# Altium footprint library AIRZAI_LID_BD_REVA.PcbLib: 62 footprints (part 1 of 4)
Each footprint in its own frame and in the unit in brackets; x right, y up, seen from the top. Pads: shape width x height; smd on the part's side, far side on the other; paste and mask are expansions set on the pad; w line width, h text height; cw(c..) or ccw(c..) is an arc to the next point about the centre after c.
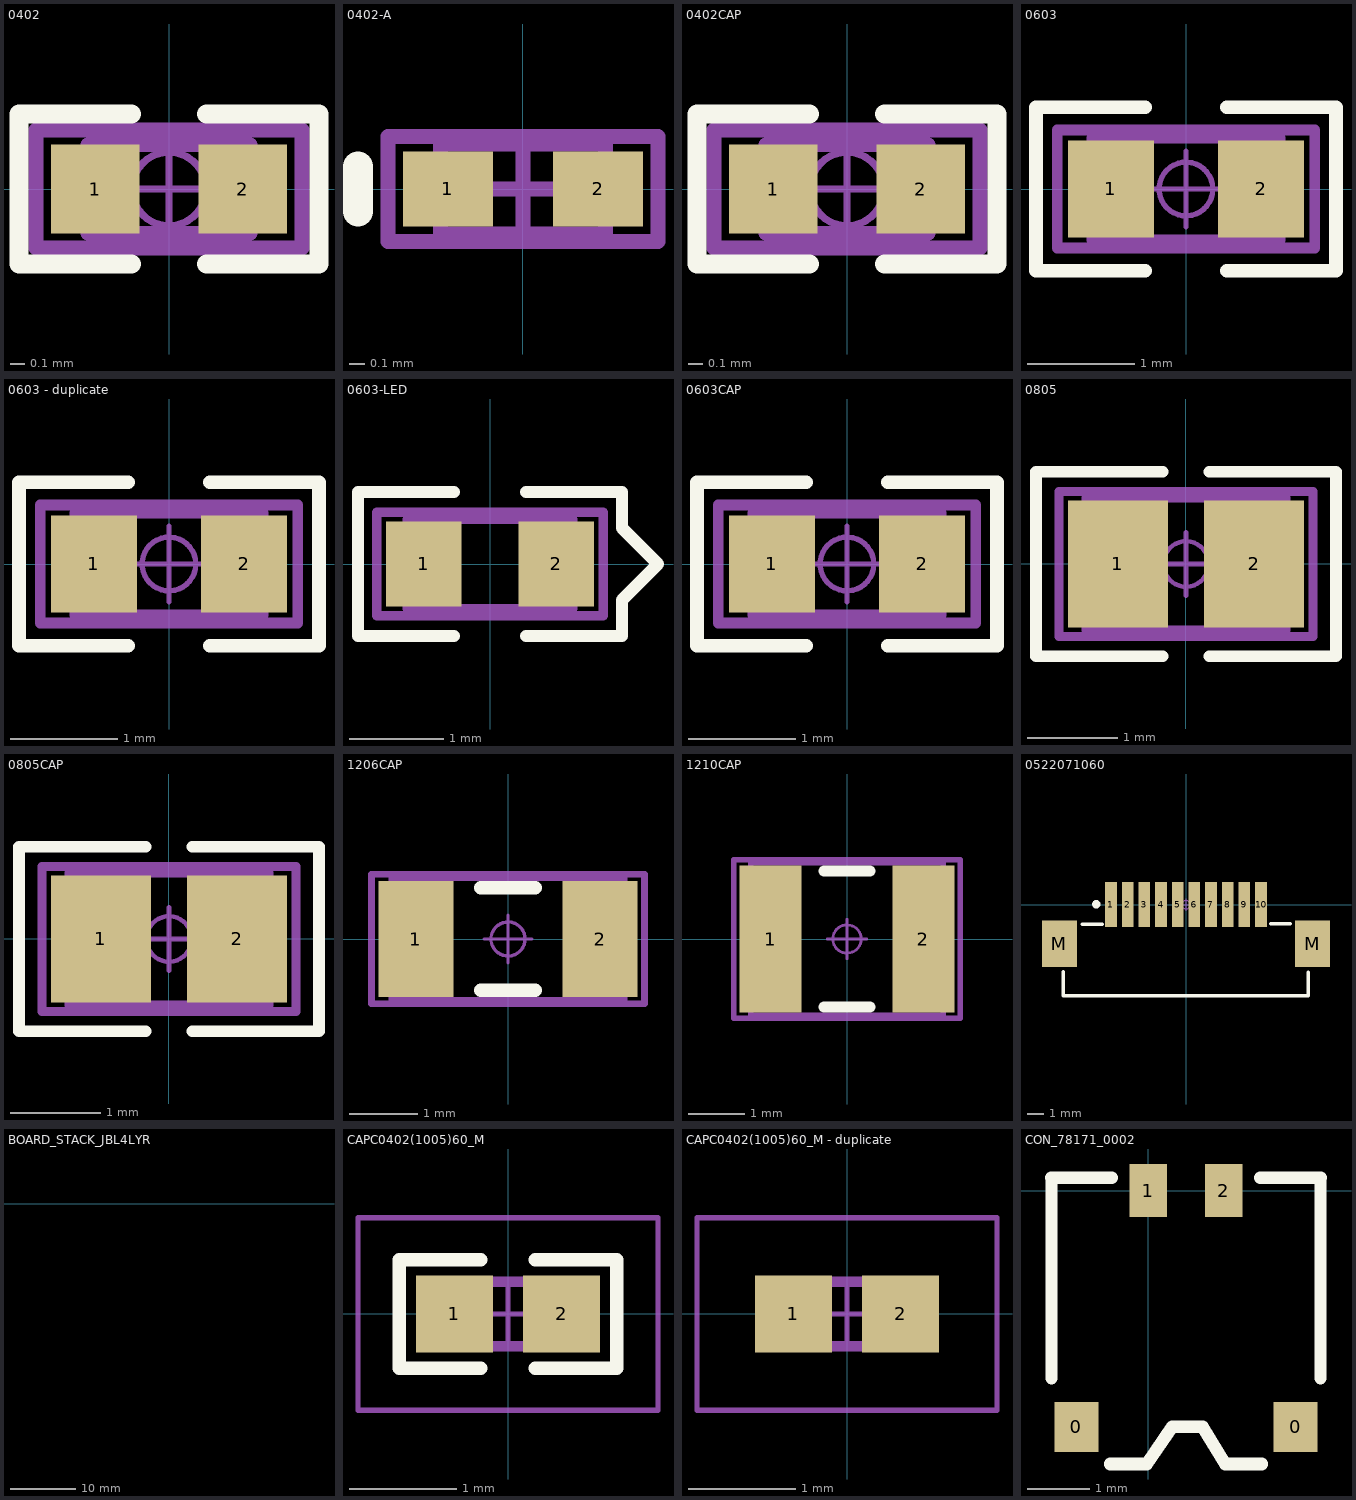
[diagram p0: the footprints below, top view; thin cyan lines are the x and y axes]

## 0402 [mm] "Chip Resistor, Body 1.1x0.5mm, IPC High Density"
height 0.4
pads (2):
  rect 0.6x0.6 smd: 1(-0.5,0) 2(0.5,0)
Top Overlay:
  lines w0.127: -0.254,-0.508 -1.016,-0.508 -1.016,0.508 -0.254,0.508 ; 0.254,-0.508 1.016,-0.508 1.016,0.508 0.254,0.508
Mechanical 1:
  text ".Designator" at -0.878,-0.254 h0.51
Mechanical 13:
  lines w0.1: -0.55,-0.3 -0.55,0.3 0.55,0.3 0.55,-0.3 -0.55,-0.3
Mechanical 15:
  circle w0.05: c0,0 r0.25
  lines w0.05: -0.35,0 0.35,0 ; 0,-0.35 0,0.35
  lines w0.1: -0.9,-0.4 -0.9,0.4 0.9,0.4 0.9,-0.4 -0.9,-0.4
3D body "R0402.step": height 0.27, standoff 0, extent -0.5,-0.254 0.5,0.248

## 0402-A [mm] "Chip Inductor, Body 1.0x0.5mm, IPC High Density"
height 0.55
pads (2):
  rect 0.6x0.5 smd: 1(-0.5,0) 2(0.5,0)
Top Overlay:
  lines w0.2: -1.1,-0.15 -1.1,0.15
Mechanical 13:
  lines w0.1: -0.55,-0.3 -0.55,0.3 0.55,0.3 0.55,-0.3 -0.55,-0.3
Mechanical 15:
  lines w0.1: -0.3,0 0.3,0 ; 0,-0.3 0,0.3 ; -0.9,-0.35 -0.9,0.35 0.9,0.35 0.9,-0.35 -0.9,-0.35
3D body: height 0.55, standoff 0, extent -0.55,-0.3 0.55,0.3

## 0402CAP [mm] "Chip Capacitor, Body 1.1x0.5mm, IPC High Density"
height 0.6
pads (2):
  rect 0.6x0.6 smd: 1(-0.5,0) 2(0.5,0)
Top Overlay:
  lines w0.127: -0.254,-0.508 -1.016,-0.508 -1.016,0.508 -0.254,0.508 ; 0.254,-0.508 1.016,-0.508 1.016,0.508 0.254,0.508
Mechanical 1:
  text ".Designator" at -0.878,-0.254 h0.51
Mechanical 13:
  lines w0.1: -0.55,-0.3 -0.55,0.3 0.55,0.3 0.55,-0.3 -0.55,-0.3
Mechanical 15:
  circle w0.05: c0,0 r0.25
  lines w0.05: -0.35,0 0.35,0 ; 0,-0.35 0,0.35
  lines w0.1: -0.9,-0.4 -0.9,0.4 0.9,0.4 0.9,-0.4 -0.9,-0.4
3D body "0402CAP.step": height 0.19, standoff -0.01, extent -0.5,-0.3 0.5,0.3

## 0603 [mm] "Chip Resistor, Body 1.6x0.8mm, IPC High Density"
height 0.55
pads (2):
  rect 0.8x0.9 smd: 1(-0.7,0) 2(0.7,0)
Top Overlay:
  lines w0.127: -0.381,-0.762 -1.397,-0.762 -1.397,0.762 -0.381,0.762 ; 0.381,-0.762 1.397,-0.762 1.397,0.762 0.381,0.762
Mechanical 1:
  text ".Designator" at -1.143,-0.254 h0.51
Mechanical 13:
  lines w0.1: -0.875,-0.475 0.875,-0.475 0.875,0.475 -0.875,0.475 -0.875,-0.475
Mechanical 15:
  circle w0.05: c0,0 r0.25
  lines w0.05: -0.35,0 0.35,0 ; 0,-0.35 0,0.35
  lines w0.1: -1.2,-0.55 1.2,-0.55 1.2,0.55 -1.2,0.55 -1.2,-0.55
3D body "R0603.step": height 0.37, standoff 0, extent -0.8,-0.406 0.8,0.396

## 0603 - duplicate [mm] "Chip Resistor, Body 1.6x0.8mm, IPC High Density"
height 0.55
pads (2):
  rect 0.8x0.9 smd: 1(-0.7,0) 2(0.7,0)
Top Overlay:
  lines w0.127: -0.381,-0.762 -1.397,-0.762 -1.397,0.762 -0.381,0.762 ; 0.381,-0.762 1.397,-0.762 1.397,0.762 0.381,0.762
Mechanical 1:
  text ".Designator" at -1.143,-0.254 h0.51
Mechanical 13:
  lines w0.1: -0.875,-0.475 -0.875,0.475 0.875,0.475 0.875,-0.475 -0.875,-0.475
Mechanical 15:
  circle w0.05: c0,0 r0.25
  lines w0.05: -0.35,0 0.35,0 ; 0,-0.35 0,0.35
  lines w0.1: -1.2,-0.55 -1.2,0.55 1.2,0.55 1.2,-0.55 -1.2,-0.55
3D body "R0603.step": height 0.37, standoff 0, extent -0.8,-0.406 0.8,0.396

## 0603-LED [mm] "Chip LED, Body 1.6x0.8mm, IPC High Density"
height 0.85
pads (2):
  rect 0.8x0.9 smd: 1(-0.7,0) 2(0.7,0)
Top Overlay:
  lines w0.127: -0.381,-0.762 -1.397,-0.762 -1.397,0.762 -0.381,0.762 ; 0.381,-0.762 1.397,-0.762 1.397,-0.381 1.778,0 1.397,0.381 1.397,0.762 0.381,0.762
Mechanical 1:
  text ".Designator" at -1.143,-0.254 h0.51
Mechanical 13:
  lines w0.1: -0.875,-0.475 0.875,-0.475 0.875,0.475 -0.875,0.475 -0.875,-0.475
Mechanical 15:
  lines w0.1: -1.2,-0.55 1.2,-0.55 1.2,0.55 -1.2,0.55 -1.2,-0.55
3D body "0603-LED.step": height 1.09, standoff 0, extent -0.799,-0.381 0.801,0.406

## 0603CAP [mm] "Chip Capacitor, Body 1.6x0.8mm, IPC High Density"
height 0.9
pads (2):
  rect 0.8x0.9 smd: 1(-0.7,0) 2(0.7,0)
Top Overlay:
  lines w0.127: -0.381,-0.762 -1.397,-0.762 -1.397,0.762 -0.381,0.762 ; 0.381,-0.762 1.397,-0.762 1.397,0.762 0.381,0.762
Mechanical 1:
  text ".Designator" at -1.143,-0.254 h0.51
Mechanical 13:
  lines w0.1: -0.875,-0.475 0.875,-0.475 0.875,0.475 -0.875,0.475 -0.875,-0.475
Mechanical 15:
  circle w0.05: c0,0 r0.25
  lines w0.05: -0.35,0 0.35,0 ; 0,-0.35 0,0.35
  lines w0.1: -1.2,-0.55 1.2,-0.55 1.2,0.55 -1.2,0.55 -1.2,-0.55
3D body "0603CAP.step": height 0.29, standoff -0.01, extent -0.8,-0.4 0.8,0.4

## 0805 [mm] "Chip Resistor, Body 2.0x1.3mm, IPC High Density"
height 1.1
pads (2):
  rect 1.1x1.4 smd: 1(-0.75,0) 2(0.75,0)
Top Overlay:
  lines w0.127: -0.254,-1.016 -1.651,-1.016 -1.651,1.016 -0.254,1.016 ; 0.254,-1.016 1.651,-1.016 1.651,1.016 0.254,1.016
Mechanical 1:
  text ".Designator" at -1.397,-0.254 h0.51
Mechanical 13:
  lines w0.1: -1.1,-0.725 -1.1,0.725 1.1,0.725 1.1,-0.725 -1.1,-0.725
Mechanical 15:
  circle w0.05: c0,0 r0.25
  lines w0.05: -0.35,0 0.35,0 ; 0,-0.35 0,0.35
  lines w0.1: -1.4,-0.8 -1.4,0.8 1.4,0.8 1.4,-0.8 -1.4,-0.8
3D body "R0805.step": height 0.47, standoff 0, extent -1.016,-0.635 0.984,0.617

## 0805CAP [mm] "Chip Capacitor, Body 2.0x1.3mm, IPC High Density"
height 1.4
pads (2):
  rect 1.1x1.4 smd: 1(-0.75,0) 2(0.75,0)
Top Overlay:
  lines w0.127: -0.254,-1.016 -1.651,-1.016 -1.651,1.016 -0.254,1.016 ; 0.254,-1.016 1.651,-1.016 1.651,1.016 0.254,1.016
Mechanical 1:
  text ".Designator" at -1.397,-0.254 h0.51
Mechanical 13:
  lines w0.1: -1.1,-0.725 -1.1,0.725 1.1,0.725 1.1,-0.725 -1.1,-0.725
Mechanical 15:
  circle w0.05: c0,0 r0.25
  lines w0.05: -0.35,0 0.35,0 ; 0,-0.35 0,0.35
  lines w0.1: -1.4,-0.8 -1.4,0.8 1.4,0.8 1.4,-0.8 -1.4,-0.8
3D body "0805CAP.step": height 0.78, standoff 0, extent -1,-0.625 1,0.625

## 1206CAP [mm] "Chip Capacitor, Body 3.2x1.6mm, IPC High Density"
height 1.8
pads (2):
  rect 1.1x1.7 smd: 1(-1.35,0) 2(1.35,0)
Top Overlay:
  lines w0.2: -0.4,-0.75 0.4,-0.75 ; -0.4,0.75 0.4,0.75
Mechanical 1:
  text ".Designator" at -1.143,-0.254 h0.51
Mechanical 13:
  lines w0.1: -1.7,-0.9 1.7,-0.9 1.7,0.9 -1.7,0.9 -1.7,-0.9
Mechanical 15:
  circle w0.05: c0,0 r0.25
  lines w0.05: -0.35,0 0.35,0 ; 0,-0.35 0,0.35
  lines w0.1: -2,-0.95 2,-0.95 2,0.95 -2,0.95 -2,-0.95
3D body "1206CAP.step": height 1, standoff 0, extent -1.6,-0.8 1.6,0.8

## 1210CAP [mm] "Chip Capacitor, Body 3.2x2.5mm, IPC High Density"
height 2.5
pads (2):
  rect 1.1x2.6 smd: 1(-1.35,0) 2(1.35,0)
Top Overlay:
  lines w0.2: -0.4,-1.2 0.4,-1.2 ; -0.4,1.2 0.4,1.2
Mechanical 1:
  text ".Designator" at -1.092,-0.254 h0.51
Mechanical 13:
  lines w0.1: -1.7,-1.35 -1.7,1.35 1.7,1.35 1.7,-1.35 -1.7,-1.35
Mechanical 15:
  circle w0.05: c0,0 r0.25
  lines w0.05: -0.35,0 0.35,0 ; 0,-0.35 0,0.35
  lines w0.1: -2,-1.4 -2,1.4 2,1.4 2,-1.4 -2,-1.4
3D body "1210 CAP.step": height 2.5, standoff 0, extent -1.6,-1.25 1.6,1.25

## 0522071060 [mm]
pads (12):
  rect 0.7x2.7 smd: 1(-4.5,0) 2(-3.5,0) 3(-2.5,0) 4(-1.5,0) 5(-0.5,0) 6(0.5,0) 7(1.5,0) 8(2.5,0) 9(3.5,0) 10(4.5,0)
  rect 2.1x2.8 smd: M(-7.6,-2.35) M(7.6,-2.35)
Top Overlay:
  circle w0.25: c-5.385,0.025 r0.125
  lines w0.2: -7.366,-5.468 -7.366,-4.029 ; -7.35,-5.468 7.341,-5.468 7.341,-4.039 ; -6.223,-1.168 -5.029,-1.168 ; 5.08,-1.143 6.274,-1.143
Mechanical 1:
  text ".Designator" at -3.607,-3.81 h0.76
Mechanical 15:
  circle w0.05: c0,0 r0.25
  lines w0.05: -0.35,0 0.35,0 ; 0,-0.35 0,0.35
3D body "522071060.stp": height 2.65, standoff -0.05, extent -8.15,-8.113 8.15,0.787

## BOARD_STACK_JBL4LYR [mm]
height 1.6
Drill Drawing:
  lines w0.3: 26.507,-19.006 26.507,-14.007 72.725,-14.007 72.725,-19.006 26.507,-19.006 ; 29.507,-30.005 29.507,-25.006 63.504,-25.006 63.504,-30.005 29.507,-30.005 ; 29.507,-8.007 29.507,-3.008 63.504,-3.008 63.504,-8.007 29.507,-8.007
  lines w1: 28.507,-34.005 66.504,-34.005 ; 28.507,-22.006 66.504,-22.006 ; 28.507,-12.007 66.504,-12.007 ; 28.507,-0.008 66.504,-0.008
  text "TOTAL BOARD THICKNESS .80" at 30.325,-39.5 h2.25
  text "0.132MM" at 39.017,-7.063 h2.25
  text "1OZ. CU" at 71.014,-36.061 h2.25
  text "1OZ. CU" at 70.014,-24.062 h2.25
  text "1OZ. CU" at 71.014,-13.063 h2.25
  text "1OZ. CU" at 70.014,-2.064 h2.25
  text "BOT LAYER" at 2.02,-36.061 h3
  text "IN2 LAYER" at 1.02,-24.062 h3
  text "IN1 LAYER" at 1.02,-14.062 h3
  text "TOP LAYER" at 0.02,-3.063 h3
  text "DIMENSIONS ARE IN MM" at 23.478,-44.965 h2.25
  text "ADJUST TO THICKNESS" at 29.017,-18.062 h2.25
  text "0.132MM" at 40.016,-29.061 h2.25

## CAPC0402(1005)60_M [mm] "Chip Capacitor, Body 1.0x0.5mm, Height 0.6mm, IPC Low Density"
height 0.6
pads (2):
  rect 0.72x0.72 smd: 1(-0.5,0) 2(0.5,0)
Top Overlay:
  lines w0.127: -0.254,-0.508 -1.016,-0.508 -1.016,0.508 -0.254,0.508 ; 0.254,-0.508 1.016,-0.508 1.016,0.508 0.254,0.508
Mechanical 13:
  lines w0.1: -0.55,-0.3 -0.55,0.3 0.55,0.3 0.55,-0.3 -0.55,-0.3
Mechanical 15:
  lines w0.05: -0.3,0 0.3,0 ; 0,-0.3 0,0.3 ; -1.4,-0.9 -1.4,0.9 1.4,0.9 1.4,-0.9 -1.4,-0.9
3D body: height 0.6, standoff 0, extent -0.3,-0.3 0.3,0.3
3D body: height 0.6, standoff 0, extent -0.55,-0.3 -0.3,0.3
3D body: height 0.6, standoff 0, extent 0.3,-0.3 0.55,0.3

## CAPC0402(1005)60_M - duplicate [mm] "Chip Capacitor, Body 1.0x0.5mm, Height 0.6mm, IPC Low Density"
height 0.6
pads (2):
  rect 0.72x0.72 smd: 1(-0.5,0) 2(0.5,0)
Mechanical 13:
  lines w0.1: -0.55,-0.3 0.55,-0.3 0.55,0.3 -0.55,0.3 -0.55,-0.3
Mechanical 15:
  lines w0.05: -0.3,0 0.3,0 ; 0,-0.3 0,0.3 ; -1.4,-0.9 1.4,-0.9 1.4,0.9 -1.4,0.9 -1.4,-0.9
3D body: height 0.6, standoff 0, extent 0.3,-0.3 0.55,0.3
3D body: height 0.6, standoff 0, extent -0.55,-0.3 -0.3,0.3
3D body: height 0.6, standoff 0, extent -0.3,-0.3 0.3,0.3

## CON_78171_0002 [mm] "1.55 MATED HT"
height 1.45
pads (4):
  rect 0.7x0.8 smd mask+0.1: 0(-1.15,-3.775) 0(2.35,-3.775)
  rect 0.6x0.85 smd mask+0.1: 1(0,0) 2(1.2,0)
Top Overlay:
  lines w0.198: -1.549,-2.997 -1.549,0.203 ; 2.749,-2.997 2.749,0.203
  lines w0.2: -1.549,0.203 -0.585,0.203 ; -0.61,-4.369 -0.025,-4.369 0.381,-3.775 0.864,-3.775 1.225,-4.369 1.81,-4.369 ; 1.785,0.203 2.749,0.203
3D body "conn_molex_781710002_4.stp": height 1.44, standoff -0.01, extent -1.5,-4.327 2.7,0.202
